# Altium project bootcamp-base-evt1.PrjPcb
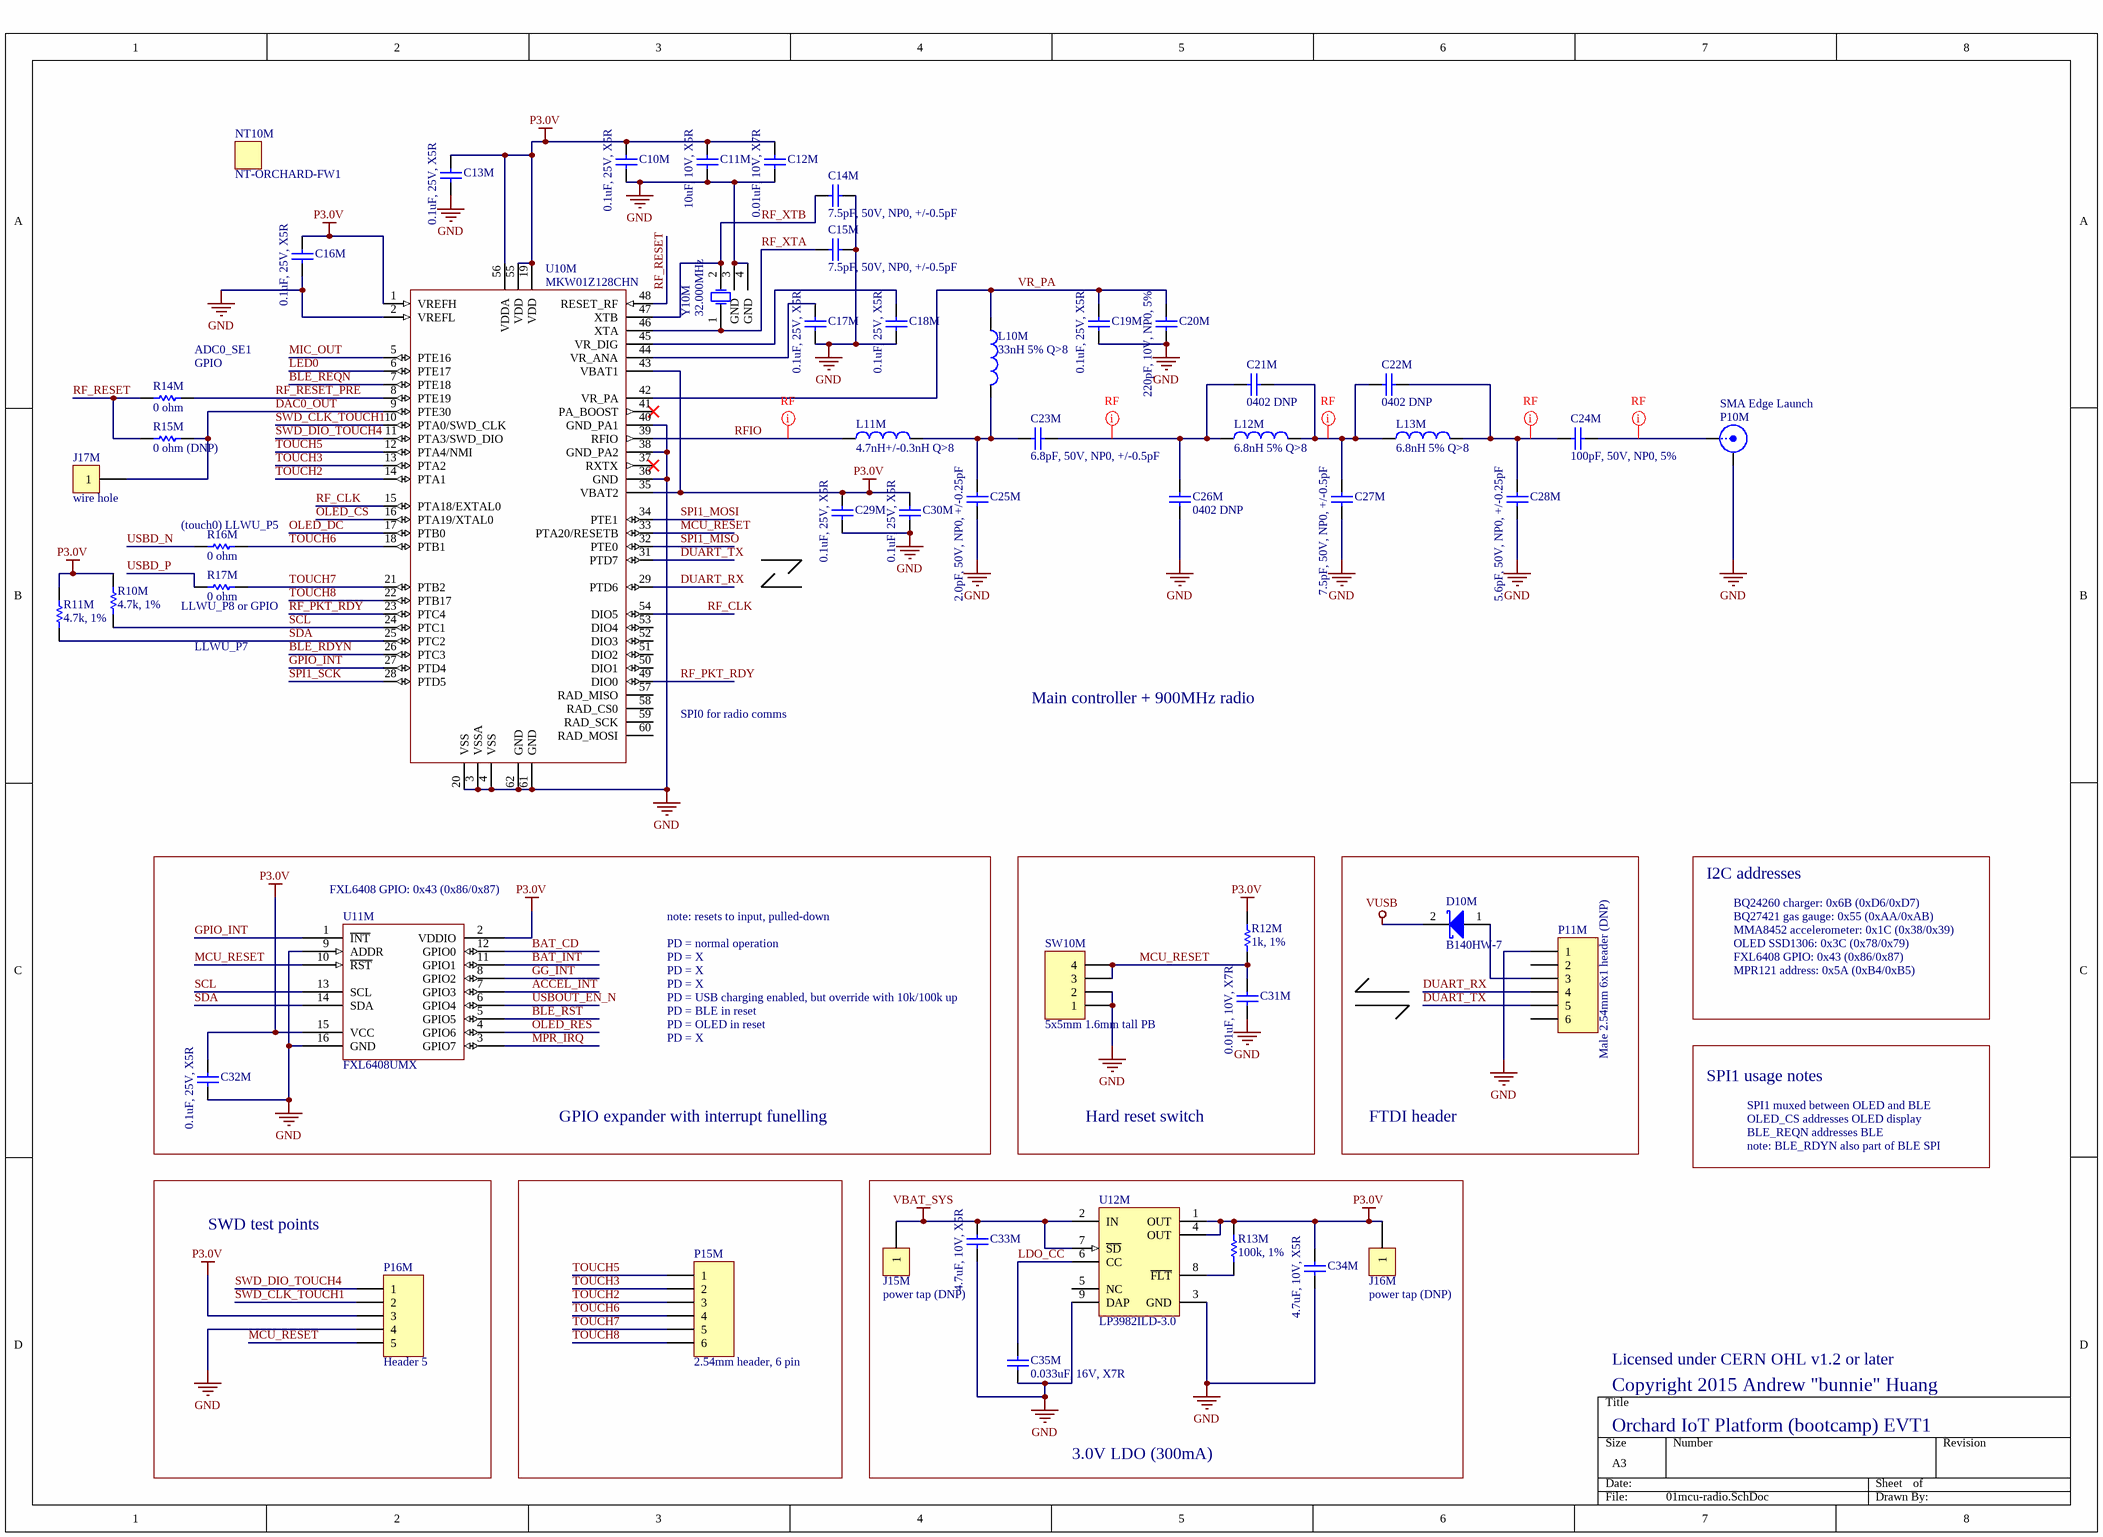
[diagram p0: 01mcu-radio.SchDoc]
7 sheets, 180 parts. Net scope: global (net labels, ports and power ports of the same name join across sheets).
Board files: bootcamp-base-evt1b.PcbDoc, bootcamp-base-evt1-local-routes-handoff.PcbDoc
Sheets:
  01mcu-radio.SchDoc
  02battery.SchDoc
  03sensors.SchDoc
  04oled.SchDoc
  05ble.SchDoc
  06led.SchDoc
  07captouch.SchDoc

## Sheet 01mcu-radio.SchDoc
size A3

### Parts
C10M  0.1uF, 25V, X5R  [CAPC1005N]
C11M  10uF, 10V, X5R  [CAPC1608N]
C12M  0.01uF, 10V, X7R  [CAPC1005N]
C13M  0.1uF, 25V, X5R  [CAPC1005N]
C14M  7.5pF, 50V, NP0, +/-0.5pF  [CAPC1005N]
C15M  7.5pF, 50V, NP0, +/-0.5pF  [CAPC1005N]
C16M  0.1uF, 25V, X5R  [CAPC1005N]
C17M  0.1uF, 25V, X5R  [CAPC1005N]
C18M  0.1uF, 25V, X5R  [CAPC1005N]
C19M  0.1uF, 25V, X5R  [CAPC1005N]
C20M  220pF, 10V, NP0, 5%  [CAPC1005N]
C21M  0402 DNP  [CAPC1005N]
C22M  0402 DNP  [CAPC1005N]
C23M  6.8pF, 50V, NP0, +/-0.5pF  [CAPC1005N]
C24M  100pF, 50V, NP0, 5%  [CAPC1005N]
C25M  2.0pF, 50V, NP0, +/-0.25pF  [CAPC1005N]
C26M  0402 DNP  [CAPC1005N]
C27M  7.5pF, 50V, NP0, +/-0.5pF  [CAPC1005N]
C28M  5.6pF, 50V, NP0, +/-0.25pF  [CAPC1005N]
C29M  0.1uF, 25V, X5R  [CAPC1005N]
C30M  0.1uF, 25V, X5R  [CAPC1005N]
C31M  0.01uF, 10V, X7R  [CAPC1005N]
C32M  0.1uF, 25V, X5R  [CAPC1005N]
C33M  4.7uF, 10V, X5R  [CAPC1608N]
C34M  4.7uF, 10V, X5R  [CAPC1608N]
C35M  0.033uF, 16V, X7R  [CAPC1005N]
D10M  B140HW-7  [SOD123]
J15M  power tap (DNP)  [RESTAP-0603]
J16M  power tap (DNP)  [RESTAP-0603]
J17M  wire hole  [TP_HOLE]
L10M  33nH 5% Q>8  [INDC1608AN]
L11M  4.7nH+/-0.3nH Q>8  [INDC1608AN]
L12M  6.8nH 5% Q>8  [INDC1608AN]
L13M  6.8nH 5% Q>8  [INDC1608AN]
NT10M  NT-ORCHARD-FW1
P10M  SMA Edge Launch  [SMA_EDGELAUNCH]
P11M  Male 2.54mm 6x1 header (DNP)  [HDR1X6]
P15M  2.54mm header, 6 pin  [HDR1X6]
P16M  Header 5  [HDR1X5]
R10M  4.7k, 1%  [RESC1005N]
R11M  4.7k, 1%  [RESC1005N]
R12M  1k, 1%  [RESC1005N]
R13M  100k, 1%  [RESC1005N]
R14M  0 ohm  [RESC1005N]
R15M  0 ohm (DNP)  [RESC1005N]
R16M  0 ohm  [RESC1005N]
R17M  0 ohm  [RESC1005N]
SW10M  5x5mm 1.6mm tall PB  [SWITCH_TS-1187A]
U10M  MKW01Z128CHN  [KINETIS_W_QFN50P800X800X98_HS-57N]
U11M  FXL6408UMX  [FAIRCHILD_UMLP16]
U12M  LP3982ILD-3.0  [LDA08C]
Y10M  32.000MHz  [NDK_NX3225SA]

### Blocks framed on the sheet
GPIO expander with interrupt funelling: C32M U11M
Hard reset switch: C31M R12M SW10M
FTDI header: D10M P11M
SWD test points: P16M
3.0V LDO (300mA): C33M C34M C35M J15M J16M R13M U12M

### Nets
GND: C10M.2 C11M.2 C12M.2 C13M.2 C14M.2 C15M.2 C16M.2 C17M.2 C18M.2 C19M.2 C20M.2 C25M.2 C26M.1 C27M.2 C28M.2 C29M.2 C30M.2 C31M.2 C32M.2 C33M.2 C34M.2 C35M.1 P10M.2(Y) P11M.1 P16M.4 SW10M.1 SW10M.2 U10M.2(VREFL) U10M.3(VSSA) U10M.4(VSS) U10M.20(VSS) U10M.36(GND) U10M.38(GND_PA2) U10M.40(GND_PA1) U10M.61(GND) U10M.62(GND) U11M.9(ADDR) U11M.16(GND) U12M.3(GND) U12M.9(DAP) Y10M.3(GND) Y10M.4(GND)
P3.0V: C10M.1 C11M.1 C12M.1 C13M.1 C16M.1 C29M.1 C30M.1 C32M.1 C34M.1 J16M.1 P16M.3 R10M.2 R11M.2 R12M.1 R13M.1 U10M.1(VREFH) U10M.19(VDD) U10M.35(VBAT2) U10M.43(VBAT1) U10M.55(VDD) U10M.56(VDDA) U11M.2(VDDIO) U11M.15(VCC) U12M.1(OUT) U12M.4(OUT)
VBAT_SYS: C33M.1 J15M.1 U12M.2(IN) U12M.7(~{SD})
VUSB: D10M.2(K)
ACCEL_INT: U11M.7(GPIO3)
BAT_CD: U11M.12(GPIO0)
BAT_INT: U11M.11(GPIO1)
BLE_RDYN: U10M.26(PTC3)
BLE_REQN: U10M.7(PTE18)
BLE_RST: U11M.5(GPIO5)
DAC0_OUT: J17M.1 R15M.2 U10M.9(PTE30)
DUART_RX: P11M.4 U10M.29(PTD6)
DUART_TX: P11M.5 U10M.31(PTD7)
GG_INT: U11M.8(GPIO2)
GPIO_INT: U10M.27(PTD4) U11M.1(~{INT})
LDO_CC: C35M.2 U12M.6(CC)
LED0: U10M.6(PTE17)
MCU_RESET: C31M.1 P16M.5 R12M.2 SW10M.3 SW10M.4 U10M.33(PTA20/RESETB) U11M.10(~{RST})
MIC_OUT: U10M.5(PTE16)
MPR_IRQ: U11M.3(GPIO7)
OLED_CS: U10M.16(PTA19/XTAL0)
OLED_DC: U10M.17(PTB0)
OLED_RES: U11M.4(GPIO6)
RF_CLK: U10M.15(PTA18/EXTAL0) U10M.54(DIO5)
RF_PKT_RDY: U10M.23(PTC4) U10M.49(DIO0)
RF_RESET: R14M.1 R15M.1 U10M.48(RESET_RF)
RF_RESET_PRE: R14M.2 U10M.8(PTE19)
RF_XTA: C15M.1 U10M.46(XTA) Y10M.1(OSC1)
RF_XTB: C14M.1 U10M.47(XTB) Y10M.2(OSC2)
RFIO: L11M.1 U10M.39(RFIO)
SCL: R10M.1 U10M.24(PTC1) U11M.13(SCL)
SDA: R11M.1 U10M.25(PTC2) U11M.14(SDA)
SPI1_MISO: U10M.32(PTE0)
SPI1_MOSI: U10M.34(PTE1)
SPI1_SCK: U10M.28(PTD5)
SWD_CLK_TOUCH1: P16M.2 U10M.10(PTA0/SWD_CLK)
SWD_DIO_TOUCH4: P16M.1 U10M.11(PTA3/SWD_DIO)
TOUCH2: P15M.3 U10M.14(PTA1)
TOUCH3: P15M.2 U10M.13(PTA2)
TOUCH5: P15M.1 U10M.12(PTA4/NMI)
TOUCH6: P15M.4 R16M.2 U10M.18(PTB1)
TOUCH7: P15M.5 R17M.2 U10M.21(PTB2)
TOUCH8: P15M.6 U10M.22(PTB17)
USBD_N: R16M.1
USBD_P: R17M.1
USBOUT_EN_N: U11M.6(GPIO4)
VR_PA: C19M.1 C20M.1 L10M.1 U10M.42(VR_PA)
NetC17M_1: C17M.1 U10M.44(VR_ANA)
NetC18M_1: C18M.1 U10M.45(VR_DIG)
NetC21M_1: C21M.1 C23M.2 C26M.2 L12M.1
NetC21M_2: C21M.2 C22M.1 C27M.1 L12M.2 L13M.1
NetC22M_2: C22M.2 C24M.1 C28M.1 L13M.2
NetC23M_1: C23M.1 C25M.1 L10M.2 L11M.2
NetC24M_2: C24M.2 P10M.1(X)
NetD10M_1: D10M.1(A) P11M.3
NetR13M_2: R13M.2 U12M.8(~{FLT})

Not connected (* = marked no-connect by the designer): P11M 2 6; U10M 37(RXTX)* 41(PA_BOOST)* 50(DIO1) 51(DIO2) 52(DIO3) 53(DIO4) 57(RAD_MISO) 58(RAD_CS0) 59(RAD_SCK) 60(RAD_MOSI); U12M 5(NC)

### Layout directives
net class RF: NetC21M_1, NetC21M_2, NetC22M_2, NetC24M_2, RFIO

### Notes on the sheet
- (near R14M) ADC0_SE1
- (near R14M) GPIO
- (near R16M) (touch0) LLWU_P5
- (near R17M) LLWU_P8 or GPIO
- LLWU_P7
- SPI0 for radio comms
- Main controller + 900MHz radio
- I2C addresses
- (near U11M) FXL6408 GPIO: 0x43 (0x86/0x87)
- note: resets to input, pulled-down
- PD = normal operation
- BQ24260 charger: 0x6B (0xD6/0xD7)
- BQ27421 gas gauge: 0x55 (0xAA/0xAB)
- MMA8452 accelerometer: 0x1C (0x38/0x39)
- OLED SSD1306: 0x3C (0x78/0x79)
- PD = X
- PD = USB charging enabled, but override with 10k/100k up
- PD = BLE in reset
- FXL6408 GPIO: 0x43 (0x86/0x87)
- MPR121 address: 0x5A (0xB4/0xB5)
- PD = OLED in reset
- SPI1 usage notes
- SPI1 muxed between OLED and BLE
- OLED_CS addresses OLED display
- BLE_REQN addresses BLE
- note: BLE_RDYN also part of BLE SPI
- Licensed under CERN OHL v1.2 or later
- Copyright 2015 Andrew "bunnie" Huang
- Orchard IoT Platform (bootcamp) EVT1

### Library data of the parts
C10M C13M C16M C17M C18M C19M C29M C30M C32M = Cap Semi: Capacitor (Semiconductor SIM Model); MPN: CL05A104KA5NNNC; VENDOR: Samsung; MYPN: C-104-25-X5R-0402
C11M = Cap Semi: Capacitor (Semiconductor SIM Model); MPN: CL10A106KP8NNND; VENDOR: Samsung; MYPN: C-106-10-X5R-0603
C12M C31M = Cap Semi: Capacitor (Semiconductor SIM Model); MPN: CL05B103KP5NNNC; VENDOR: Samsung; MYPN: C-103-10-X7R-0402
C14M C15M C27M = Cap Semi: Capacitor (Semiconductor SIM Model); MPN: 0402CG7R5D500NT; VENDOR: Fenghua; MYPN: C-7R5-50-NP0-0402
C20M = Cap Semi: Capacitor (Semiconductor SIM Model); MPN: 0402CG221J100NT; VENDOR: Fenghua; MYPN: C-221-10-NP0-0402
C21M C22M C26M = Cap Semi: Capacitor (Semiconductor SIM Model); MPN: None; MYPN: C-DNP-0402
C23M = Cap Semi: Capacitor (Semiconductor SIM Model); MPN: 0402CG6R8D500NT; VENDOR: Fenghua; MYPN: C-6R8-50-NP0-0402
C24M = Cap Semi: Capacitor (Semiconductor SIM Model); MPN: 0402CG101J500NT; VENDOR: Fenghua; MYPN: C-101-50-NP0-0402
C25M = Cap Semi: Capacitor (Semiconductor SIM Model); MPN: 0402CG2R0C500NT; VENDOR: Fenghua; MYPN: C-2R0-50-NP0-0402
C28M = Cap Semi: Capacitor (Semiconductor SIM Model); MPN: 0402CG5R6C500NT; VENDOR: Fenghua; MYPN: C-5R6-50-NP0-0402
C33M C34M = Cap Semi: Capacitor (Semiconductor SIM Model); MPN: CL10A475KP8NNNC; VENDOR: Samsung; MYPN: C-475-10-X5R-0603
C35M = Cap Semi: Capacitor (Semiconductor SIM Model); MPN: CL05B333KO5NNND; VENDOR: Samsung; MYPN: C-333-16-X7R-0402
D10M = D Schottky: Schottky Diode; VENDOR: Diodes Incorporated; MYPN: D-S-01-40-0p5-SOD123
J15M J16M = CON1: Connector; MYPN: J-TP-PWRTAP-0603
J17M = CON1: Connector; MPN: DNP; MYPN: J-TP-HOLE1
L10M = Inductor: chip inductor, 0603; MPN: VHF160808H33NJT; VENDOR: Fenghua; MYPN: L-33N-MLC-0603
L11M = Inductor: chip inductor, 0603; MPN: VHF160808H4N7ST; VENDOR: Fenghua; MYPN: L-4N7-MLC-0603
L12M L13M = Inductor: chip inductor, 0603; MPN: VHF160808H6N8JT; VENDOR: Fenghua; MYPN: L-6N8-MLC-0603
NT10M = NOTE: Placeholder for non-electrical BOM items; MPN: Orchard Firmware EVT1; VENDOR: Sutajio Ko-Usagi PTE LTD
P10M = BNC: 50 ohm SMA Edge Launch Connector; MPN: CONSMA003.062 (please find alt); MYPN: J-RF-SMA-EDGE-50OHM; VENDOR: Any/open
P11M = Header 6: Header, 6-Pin; MYPN: J-HDR-2.54-6x1-STD-DNP
P15M = Header 6: Header, 6-Pin; MYPN: DNP
P16M = Header 5: Header, 5-Pin; MPN: DNP; MYPN: J-HDR-2.54-5x1-STD-DNP
R10M R11M = Res1: Resistor; MPN: RS02U472FT; VENDOR: Fenghua; MYPN: R-472-1P-1_16W-0402
R12M = Res1: Resistor; MPN: RS02U102FT; VENDOR: Fenghua; MYPN: R-102-1P-1_16W-0402
R13M = Res1: Resistor; MPN: RS02U104FT; VENDOR: Fenghua; MYPN: R-104-1P-1_16W-0402
R14M R16M R17M = Res1: Resistor; MPN: ANY-0402-0OHM; VENDOR: ANY; MYPN: R-000-1_4W-0402
R15M = Res1: Resistor; MYPN: R-000-1_4W-0402-DNP
SW10M = Header 4: Chi Fung TS-1187A; MPN: SW-PB-5X5-1.6; VENDOR: Kangdeli
U10M = MKW01Z128CHN: Freescale Kinetis Integrated Radio + MCU, < 1GHz; MYPN: UMKW01Z128XX
U11M = FXL6408: 8-bit I2C GPIO expander; MYPN: UFXL6408UMX; VENDOR: Fairchild Semiconductor
U12M = LP3982ILD-3.0: Micropower, Ultra Low-Dropout, Low-Noise, 300mA CMOS Regulator; Manufacturer: National Semiconductor; MPN: LP3982ILD-3.0/NOPB; CompType: LDO IC; PackageTopMarking: XYTT*LTB; PowerWise: N; MYPN: ULP3982ILD-3.0/NOPB; VENDOR: National Semicondutor
Y10M = XTAL: 32 MHz, 7pF CL 10ppm 3225 SMD crystal; MPN: SJSMD3232M012F10; VENDOR: Songji; MYPN: X-32.000M-SONGJI

## Sheet 02battery.SchDoc
size A3
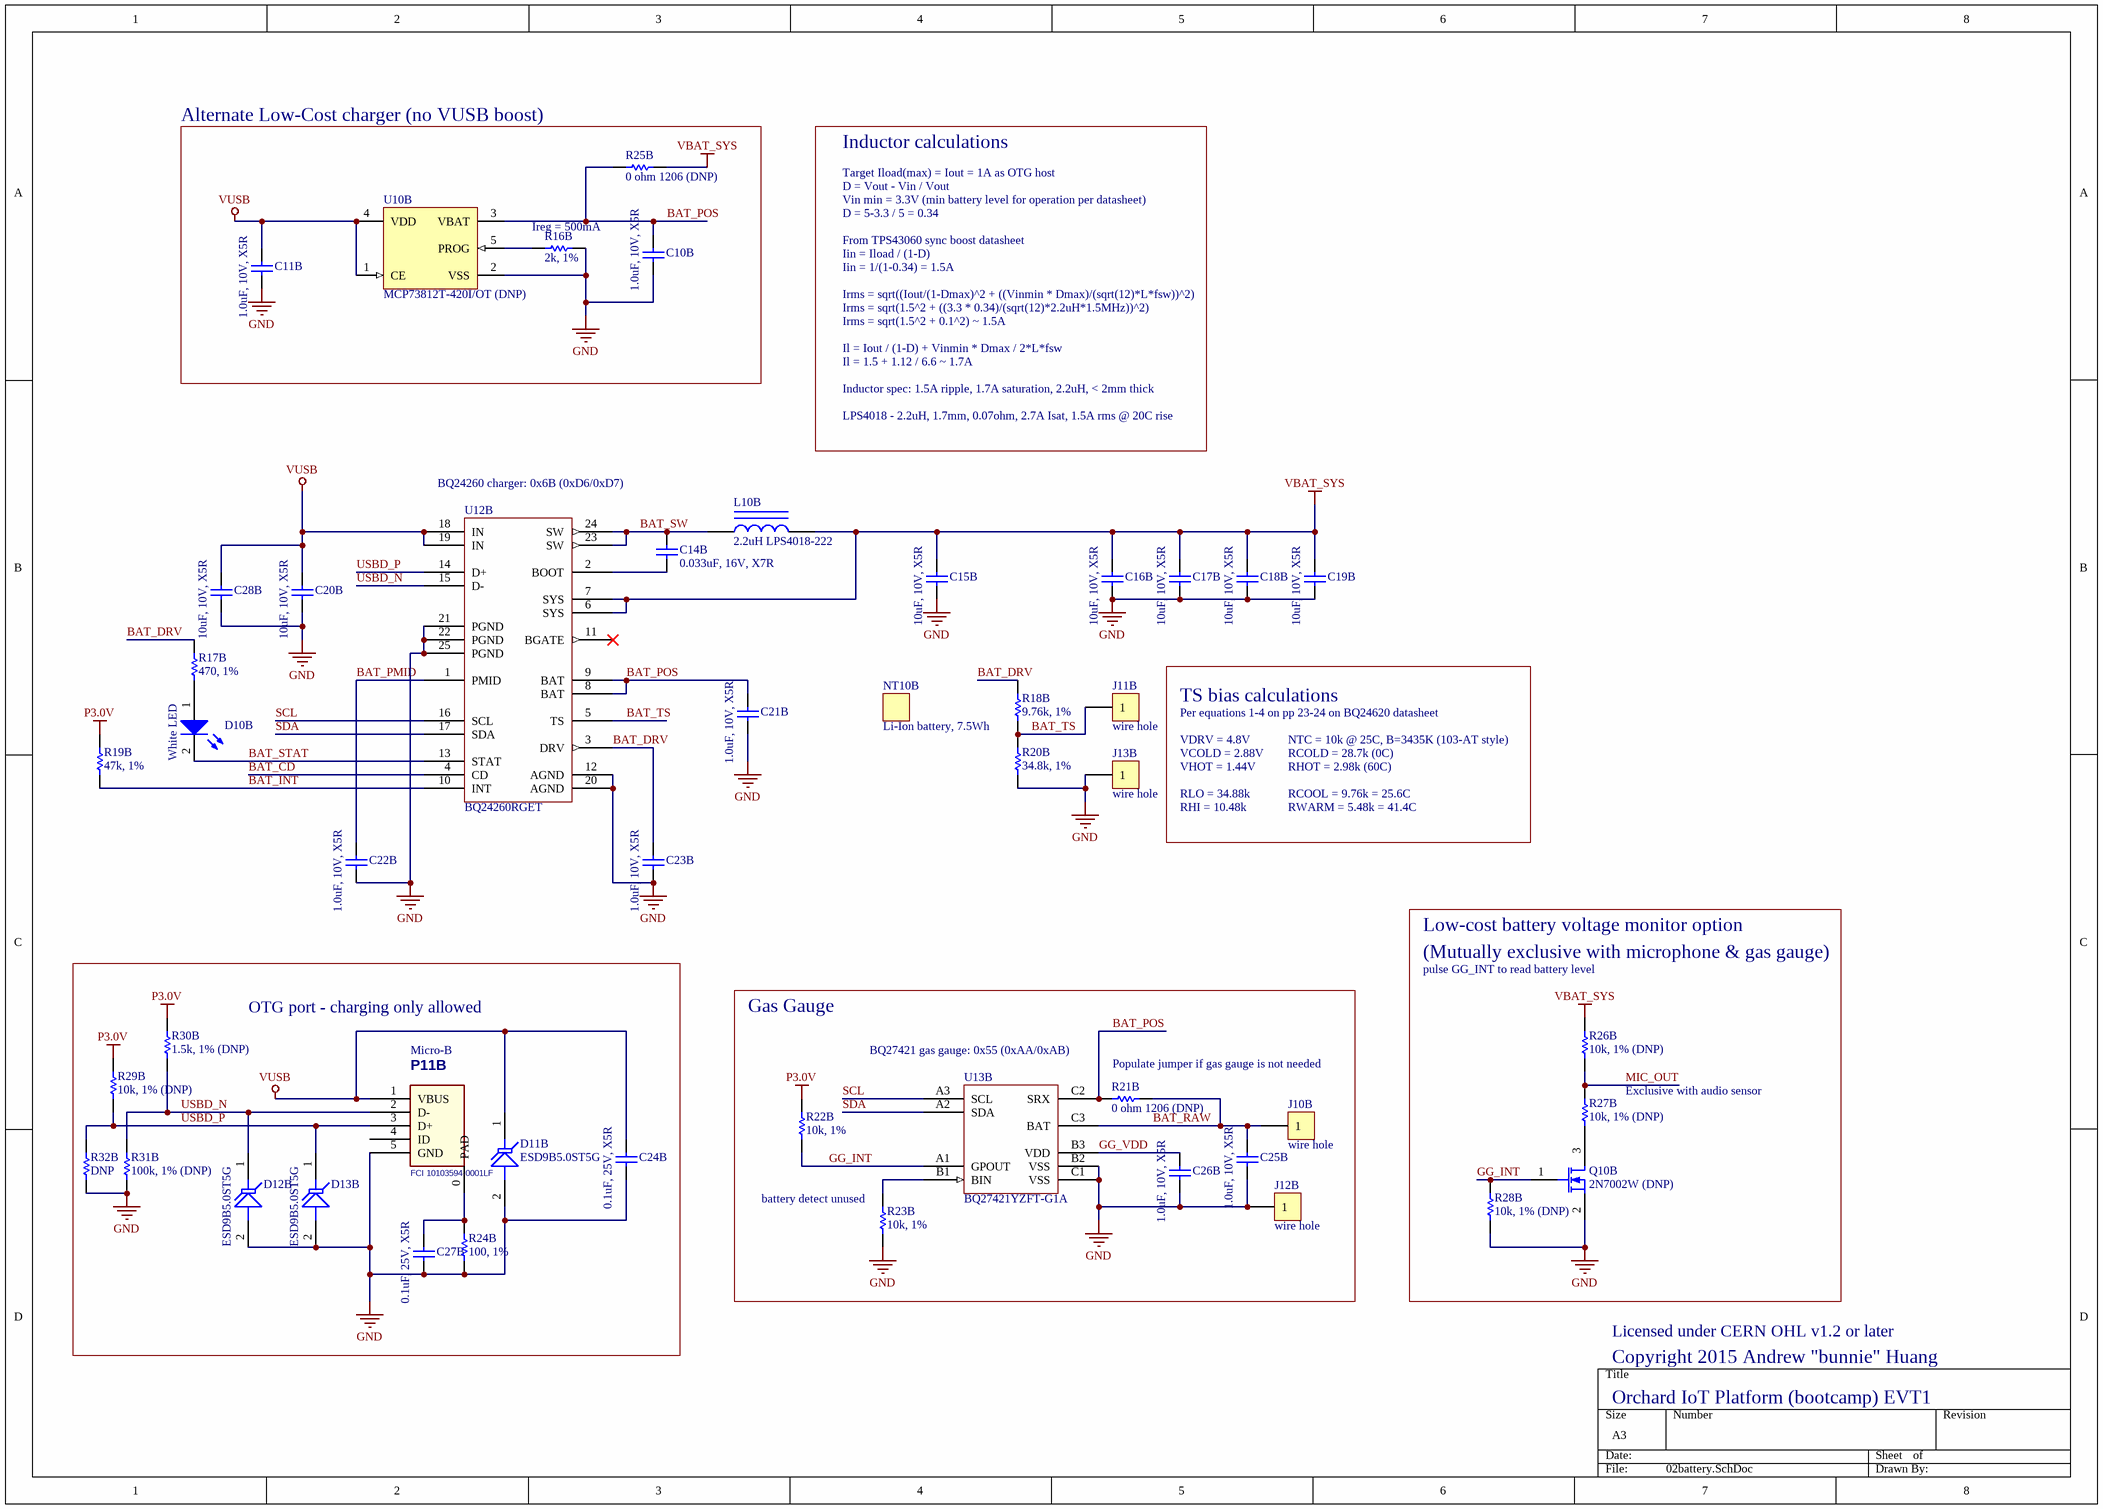
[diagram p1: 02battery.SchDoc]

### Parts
C10B  1.0uF, 10V, X5R  [CAPC1005N]
C11B  1.0uF, 10V, X5R  [CAPC1005N]
C14B  0.033uF, 16V, X7R  [CAPC1005N]
C15B  10uF, 10V, X5R  [CAPC1608N]
C16B  10uF, 10V, X5R  [CAPC1608N]
C17B  10uF, 10V, X5R  [CAPC1608N]
C18B  10uF, 10V, X5R  [CAPC1608N]
C19B  10uF, 10V, X5R  [CAPC1608N]
C20B  10uF, 10V, X5R  [CAPC1608N]
C21B  1.0uF, 10V, X5R  [CAPC1005N]
C22B  1.0uF, 10V, X5R  [CAPC1005N]
C23B  1.0uF, 10V, X5R  [CAPC1005N]
C24B  0.1uF, 25V, X5R  [CAPC1005N]
C25B  1.0uF, 10V, X5R  [CAPC1005N]
C26B  1.0uF, 10V, X5R  [CAPC1005N]
C27B  0.1uF, 25V, X5R  [CAPC1005N]
C28B  10uF, 10V, X5R  [CAPC1608N]
D10B  White LED  [CD2012-0805]
D11B  ESD9B5.0ST5G  [SOD-923]
D12B  ESD9B5.0ST5G  [SOD-923]
D13B  ESD9B5.0ST5G  [SOD-923]
J10B  wire hole  [TP_HOLE]
J11B  wire hole  [TP_HOLE]
J12B  wire hole  [TP_HOLE]
J13B  wire hole  [TP_HOLE]
L10B  2.2uH LPS4018-222  [COILCRAFT_LPS4018]
NT10B  Li-Ion battery, 7.5Wh
P11B  FCI 10103594-0001LF  [USB_MICRO_B_SMT]
Q10B  2N7002W (DNP)  [SOT323-3AN]
R16B  2k, 1%  [RESC1005N]
R17B  470, 1%  [RESC1005N]
R18B  9.76k, 1%  [RESC1005N]
R19B  47k, 1%  [RESC1005N]
R20B  34.8k, 1%  [RESC1005N]
R21B  0 ohm 1206 (DNP)  [RESC3216N]
R22B  10k, 1%  [RESC1005N]
R23B  10k, 1%  [RESC1005N]
R24B  100, 1%  [RESC1005N]
R25B  0 ohm 1206 (DNP)  [RESC3216N]
R26B  10k, 1% (DNP)  [RESC1005N]
R27B  10k, 1% (DNP)  [RESC1005N]
R28B  10k, 1% (DNP)  [RESC1005N]
R29B  10k, 1% (DNP)  [RESC1005N]
R30B  1.5k, 1% (DNP)  [RESC1005N]
R31B  100k, 1% (DNP)  [RESC1005N]
R32B  DNP  [RESC1005N]
U10B  MCP73812T-420I/OT (DNP)  [SOT-23-OT5_N]
U12B  BQ24260RGET  [QFN50P400X400-24VBN]
U13B  BQ27421YZFT-G1A  [TI_YZF_S_XBGA_N9]

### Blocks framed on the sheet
Alternate Low-Cost charger (no VUSB boost): C10B C11B R16B R25B U10B
OTG port - charging only allowed: C24B C27B D11B D12B D13B P11B R24B R29B R30B R31B R32B
Gas Gauge: C25B C26B J10B J12B R21B R22B R23B U13B

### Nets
GND: C10B.2 C11B.2 C15B.2 C16B.2 C17B.2 C18B.2 C19B.2 C20B.2 C21B.2 C22B.2 C23B.2 C24B.2 C25B.2 C26B.2 C27B.2 C28B.2 D11B.2(A) D12B.2(A) D13B.2(A) J12B.1 J13B.1 P11B.5(GND) Q10B.2(S) R16B.2 R20B.1 R23B.1 R24B.2 R28B.1 R31B.2 R32B.2 U10B.2(VSS) U12B.12(AGND) U12B.20(AGND) U12B.21(PGND) U12B.22(PGND) U12B.25(PGND) U13B.B2(VSS) U13B.C1(VSS)
P3.0V: R19B.2 R22B.2 R29B.2 R30B.2
VBAT_SYS: C15B.1 C16B.1 C17B.1 C18B.1 C19B.1 L10B.2 R25B.2 R26B.2 U12B.6(SYS) U12B.7(SYS)
VUSB: C11B.1 C20B.1 C24B.1 C28B.1 D11B.1(K) P11B.1(VBUS) U10B.1(CE) U10B.4(VDD) U12B.18(IN) U12B.19(IN)
BAT_CD: U12B.4(CD)
BAT_DRV: C23B.1 R17B.1 R18B.2 U12B.3(DRV)
BAT_INT: R19B.1 U12B.10(INT)
BAT_PMID: C22B.1 U12B.1(PMID)
BAT_POS: C10B.1 C21B.1 R21B.1 R25B.1 U10B.3(VBAT) U12B.8(BAT) U12B.9(BAT) U13B.C2(SRX)
BAT_RAW: C25B.1 J10B.1 R21B.2 U13B.C3(BAT)
BAT_STAT: D10B.2(K) U12B.13(STAT)
BAT_SW: C14B.2 L10B.1 U12B.23(SW) U12B.24(SW)
BAT_TS: J11B.1 R18B.1 R20B.2 U12B.5(TS)
GG_INT: Q10B.1(G) R22B.1 R28B.2 U13B.A1(GPOUT)
GG_VDD: C26B.1 U13B.B3(VDD)
MIC_OUT: R26B.1 R27B.2
SCL: U12B.16(SCL) U13B.A3(SCL)
SDA: U12B.17(SDA) U13B.A2(SDA)
USBD_N: D12B.1(K) P11B.2(D-) R30B.1 R31B.1 U12B.15(D-)
USBD_P: D13B.1(K) P11B.3(D+) R29B.1 R32B.1 U12B.14(D+)
NetC14B_1: C14B.1 U12B.2(BOOT)
NetC27B_1: C27B.1 P11B.0(PAD) R24B.1
NetD10B_1: D10B.1(A) R17B.2
NetQ10B_3: Q10B.3(D) R27B.1
NetR16B_1: R16B.1 U10B.5(PROG)
NetR23B_2: R23B.2 U13B.B1(BIN)

Not connected (* = marked no-connect by the designer): P11B 4(ID); U12B 11(BGATE)*

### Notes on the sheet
- Target Iload(max) = Iout = 1A as OTG host
- Inductor calculations
- (near R16B) Ireg = 500mA
- D = Vout - Vin / Vout
- D = 5-3.3 / 5 = 0.34
- Vin min = 3.3V (min battery level for operation per datasheet)
- From TPS43060 sync boost datasheet
- Iin = Iload / (1-D)
- Irms = sqrt((Iout/(1-Dmax)^2 + ((Vinmin * Dmax)/(sqrt(12)*L*fsw))^2)
- Iin = 1/(1-0.34) = 1.5A
- Irms = sqrt(1.5^2 + ((3.3 * 0.34)/(sqrt(12)*2.2uH*1.5MHz))^2)
- Il = Iout / (1-D) + Vinmin * Dmax / 2*L*fsw
- Irms = sqrt(1.5^2 + 0.1^2) ~ 1.5A
- Il = 1.5 + 1.12 / 6.6 ~ 1.7A
- Inductor spec: 1.5A ripple, 1.7A saturation, 2.2uH, < 2mm thick
- LPS4018 - 2.2uH, 1.7mm, 0.07ohm, 2.7A Isat, 1.5A rms @ 20C rise
- BQ24260 charger: 0x6B (0xD6/0xD7)
- Per equations 1-4 on pp 23-24 on BQ24620 datasheet
- TS bias calculations
- VDRV = 4.8V
- VCOLD = 2.88V
- VHOT = 1.44V
- NTC = 10k @ 25C, B=3435K (103-AT style)
- RCOLD = 28.7k (0C)
- RHOT = 2.98k (60C)
- RHI = 10.48k
- RLO = 34.88k
- RCOOL = 9.76k = 25.6C
- RWARM = 5.48k = 41.4C
- Low-cost battery voltage monitor option
- (Mutually exclusive with microphone & gas gauge)
- pulse GG_INT to read battery level
- (near P11B) Micro-B
- BQ27421 gas gauge: 0x55 (0xAA/0xAB)
- (near R21B) Populate jumper if gas gauge is not needed
- Exclusive with audio sensor
- (near R23B) battery detect unused
- Licensed under CERN OHL v1.2 or later
- Copyright 2015 Andrew "bunnie" Huang
- Orchard IoT Platform (bootcamp) EVT1

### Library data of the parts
C10B C11B C21B C22B C23B C25B C26B = Cap Semi: Capacitor (Semiconductor SIM Model); MPN: CL05A105KP5NNND; VENDOR: Samsung; MYPN: C-105-10-X5R-0402
C14B = Cap Semi: as C35M on sheet 01mcu-radio
C15B C16B C17B C18B C19B C20B C28B = Cap Semi: as C11M on sheet 01mcu-radio
C24B C27B = Cap Semi: as C10M on sheet 01mcu-radio
D10B = LED2: White LED 0805; MPN: WLUW0805A-612-I15; MYPN: D-LED-WHITE1-0805; VENDOR: Wenling
D11B D12B D13B = Tranzorb: TVS Diode, 5V; VENDOR: On Semiconductor; MYPN: D-ESD-5.0-SOD-923
J10B J11B J12B J13B = CON1: Connector; MPN: DNP; MYPN: J-TP-HOLE1
L10B = Inductor Iron: Magnetic-Core Inductor; MPN: LPS4018-222NRC; VENDOR: Coilcraft; MYPN: L-LPS4018-222
NT10B = NOTE: 2100mAh Tx61x58mm battery C=2.1A (nominal) NTC = 10k, B=3435; MPN: TBD but e.g. GM055085-PCB; MYPN: NT-LION-2100-5-50-85-HC; VENDOR: TBD
P11B = USB_MINI-AB_1: Micro USB B type connector; VENDOR: FCI/BERG; MYPN: J-MICROUSB-SMT-FCI
Q10B = MOSFET-N: N-Channel MOSFET; MYPN: Q-NMOS-LP-LV-DNP
R16B = Res1: Resistor; MPN: RS02U202FT; VENDOR: Fenghua; MYPN: R-202-1P-1_16W-0402
R17B = Res1: Resistor; MPN: RS02U471FT; VENDOR: Fenghua; MYPN: R-471-1P-1_16W-0402
R18B = Res1: Resistor; MPN: RS02U9761FT; VENDOR: Fenghua; MYPN: R-9761-1P-1_16W-0402
R19B = Res1: Resistor; MPN: RS02U473FT; VENDOR: Fenghua; MYPN: R-473-1P-1_16W-0402
R20B = Res1: Resistor; MPN: RS02U3482FT; VENDOR: Fenghua; MYPN: R-3482-1P-1_16W-0402
R21B R25B = Res1: Resistor; MYPN: R-000-1_4W-1206-DNP
R22B R23B = Res1: Resistor; MPN: RS02U103FT; VENDOR: Fenghua; MYPN: R-103-1P-1_16W-0402
R24B = Res1: Resistor; MPN: RS02U101FT; VENDOR: Fenghua; MYPN: R-101-1P-1_16W-0402
R26B R27B R28B R29B = Res1: Resistor; MYPN: R-103-1P-1_16W-0402-DNP
R30B = Res1: Resistor; MYPN: R-152-1P-1_16W-0402-DNP
R31B = Res1: Resistor; MYPN: R-104-1P-1_16W-0402-DNP
R32B = Res1: Resistor
U10B = MCP73812T-420I/OT: Simple, Miniature Single-Cell, Fully Integrated Li-Ion/Li-Polymer Charge Management Controller, 4.2V, 5-Pin SOT-23, Industrial Temperature, Tape and Reel; Manufacturer: Microchip; VENDOR: Microchip Technology, Inc.; MYPN: UMCP73812T-420I/OT-DNP
U12B = BQ24260/1/2RGE: 3A, 30V host-controlled single cell Li-ion battery charger; VENDOR: Texas Instruments
U13B = BQ27421YZFT-G1A: System-side Impedance Track Gas Gauge; VENDOR: Texas Instruments; MYPN: UBQ27421YZFT-G1A

## Sheet 03sensors.SchDoc
size A
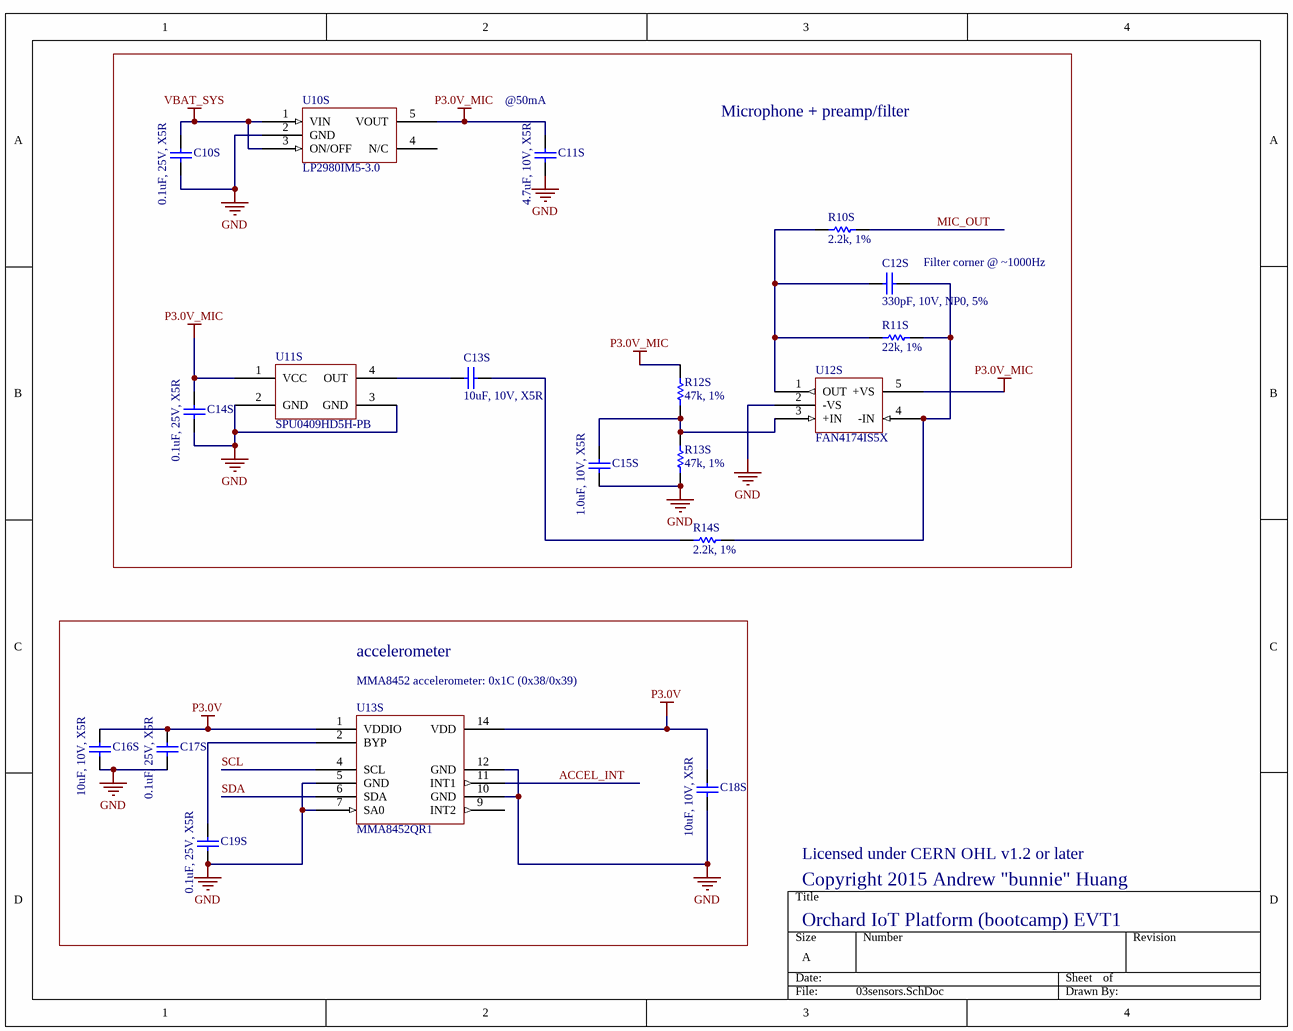
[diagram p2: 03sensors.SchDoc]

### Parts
C10S  0.1uF, 25V, X5R  [CAPC1005N]
C11S  4.7uF, 10V, X5R  [CAPC1608N]
C12S  330pF, 10V, NP0, 5%  [CAPC1005N]
C13S  10uF, 10V, X5R  [CAPC1608N]
C14S  0.1uF, 25V, X5R  [CAPC1005N]
C15S  1.0uF, 10V, X5R  [CAPC1005N]
C16S  10uF, 10V, X5R  [CAPC1608N]
C17S  0.1uF, 25V, X5R  [CAPC1005N]
C18S  10uF, 10V, X5R  [CAPC1608N]
C19S  0.1uF, 25V, X5R  [CAPC1005N]
R10S  2.2k, 1%  [RESC1005N]
R11S  22k, 1%  [RESC1005N]
R12S  47k, 1%  [RESC1005N]
R13S  47k, 1%  [RESC1005N]
R14S  2.2k, 1%  [RESC1005N]
U10S  LP2980IM5-3.0  [SOT23-5AN]
U11S  SPU0409HD5H-PB  [KNOWLES_SPU0409HD5H-PB]
U12S  FAN4174IS5X  [SOT23-5AN]
U13S  MMA8452QR1  [FSC_QFN_3x3x1_16_2077-02]

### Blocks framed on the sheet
Microphone + preamp/filter: C10S C11S C12S C13S C14S C15S R10S R11S R12S R13S R14S U10S U11S U12S
accelerometer: C16S C17S C18S C19S U13S

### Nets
GND: C10S.2 C11S.2 C14S.2 C15S.2 C16S.2 C17S.2 C18S.2 C19S.2 R13S.1 U10S.2(GND) U11S.2(GND) U11S.3(GND) U12S.2(-VS) U13S.5(GND) U13S.7(SA0) U13S.10(GND) U13S.12(GND)
P3.0V: C16S.1 C17S.1 C18S.1 U13S.1(VDDIO) U13S.14(VDD)
P3.0V_MIC: C11S.1 C14S.1 R12S.2 U10S.5(VOUT) U11S.1(VCC) U12S.5(+VS)
VBAT_SYS: C10S.1 U10S.1(VIN) U10S.3(ON/OFF)
ACCEL_INT: U13S.11(INT1)
MIC_OUT: R10S.1
SCL: U13S.4(SCL)
SDA: U13S.6(SDA)
NetC12S_1: C12S.1 R10S.2 R11S.2 U12S.1(OUT)
NetC12S_2: C12S.2 R11S.1 R14S.1 U12S.4(-IN)
NetC13S_1: C13S.1 U11S.4(OUT)
NetC13S_2: C13S.2 R14S.2
NetC15S_1: C15S.1 R12S.1 R13S.2 U12S.3(+IN)
NetC19S_1: C19S.1 U13S.2(BYP)

Not connected (* = marked no-connect by the designer): U10S 4(N/C); U13S 9(INT2)

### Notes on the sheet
- (near C11S) @50mA
- (near C12S) Filter corner @
  000Hz
- (near U13S) MMA8452 accelerometer: 0x1C (0x38/0x39)
- Licensed under CERN OHL v1.2 or later
- Copyright 2015 Andrew "bunnie" Huang
- Orchard IoT Platform (bootcamp) EVT1

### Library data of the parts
C10S C14S C17S C19S = Cap Semi: as C10M on sheet 01mcu-radio
C11S = Cap Semi: as C33M on sheet 01mcu-radio
C12S = Cap Semi: Capacitor (Semiconductor SIM Model); MPN: 0402CG331J100NT; VENDOR: Fenghua; MYPN: C-331-10-NP0-0402
C13S C16S C18S = Cap Semi: as C11M on sheet 01mcu-radio
C15S = Cap Semi: as C10B on sheet 02battery
R10S R14S = Res1: Resistor; MPN: RS02U222FT; VENDOR: Fenghua; MYPN: R-222-1P-1_16W-0402
R11S = Res1: Resistor; MPN: RS02U223FT; VENDOR: Fenghua; MYPN: R-223-1P-1_16W-0402
R12S R13S = Res1: as R19B on sheet 02battery
U10S = LP2980M5: 50 mA SOT-23 regulator; VENDOR: TI; MYPN: ULP2980IM5-3.0
U11S = SPU0409HD5H-PB: Knowles MEMS silicon microphone; MPN: SPU0409HD5H-PB-7; MYPN: USPU0409HD5H-PB-7; VENDOR: Knowles Electronics
U12S = FAN4174IS5X: Rail-to-rail single CMOS op-amp, 5V, 3.7MHz GBW; VENDOR: Fairchild Semiconductor; MYPN: UFAN4174IS5X
U13S = MMA8452QR1: 3-axis, 12-bit/8-bit digital accelerometer; MPN: MMA8452QT; MYPN: UMMA8452QT; VENDOR: Freescale Semiconductor

## Sheet 04oled.SchDoc
size A
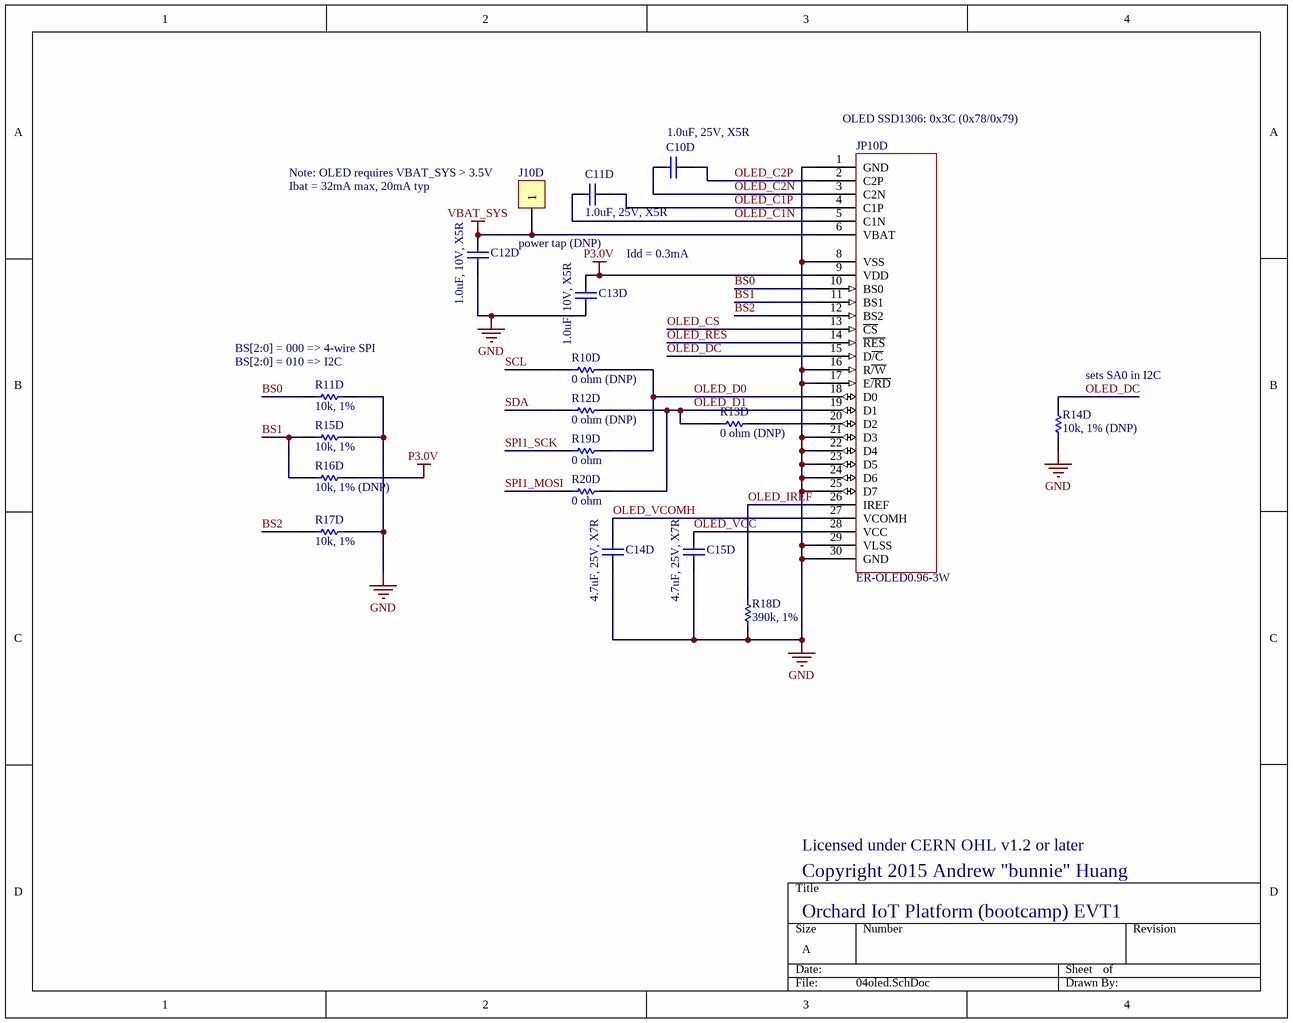
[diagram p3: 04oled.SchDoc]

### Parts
C10D  1.0uF, 25V, X5R  [CAPC1608N]
C11D  1.0uF, 25V, X5R  [CAPC1608N]
C12D  1.0uF, 10V, X5R  [CAPC1005N]
C13D  1.0uF, 10V, X5R  [CAPC1005N]
C14D  4.7uF, 25V, X7R  [CAPC2012N]
C15D  4.7uF, 25V, X7R  [CAPC2012N]
J10D  power tap (DNP)  [RESTAP-0603]
JP10D  ER-OLED0.96-3W  [ER-OLED0.96-FOLD]
R10D  0 ohm (DNP)  [RESC1005N]
R11D  10k, 1%  [RESC1005N]
R12D  0 ohm (DNP)  [RESC1005N]
R13D  0 ohm (DNP)  [RESC1005N]
R14D  10k, 1% (DNP)  [RESC1005N]
R15D  10k, 1%  [RESC1005N]
R16D  10k, 1% (DNP)  [RESC1005N]
R17D  10k, 1%  [RESC1005N]
R18D  390k, 1%  [RESC1005N]
R19D  0 ohm  [RESC1005N]
R20D  0 ohm  [RESC1005N]

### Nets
GND: C12D.2 C13D.2 C14D.2 C15D.2 JP10D.1(GND) JP10D.8(VSS) JP10D.16(R~{/W}) JP10D.17(E~{/RD}) JP10D.21(D3) JP10D.22(D4) JP10D.23(D5) JP10D.24(D6) JP10D.25(D7) JP10D.29(VLSS) JP10D.30(GND) R11D.1 R14D.2 R15D.1 R17D.1 R18D.2
P3.0V: C13D.1 JP10D.9(VDD) R16D.1
VBAT_SYS: C12D.1 J10D.1 JP10D.6(VBAT)
BS0: JP10D.10(BS0) R11D.2
BS1: JP10D.11(BS1) R15D.2 R16D.2
BS2: JP10D.12(BS2) R17D.2
OLED_C1N: C11D.1 JP10D.5(C1N)
OLED_C1P: C11D.2 JP10D.4(C1P)
OLED_C2N: C10D.1 JP10D.3(C2N)
OLED_C2P: C10D.2 JP10D.2(C2P)
OLED_CS: JP10D.13(~{CS})
OLED_D0: JP10D.18(D0) R10D.1 R19D.1
OLED_D1: JP10D.19(D1) R12D.1 R13D.2 R20D.1
OLED_DC: JP10D.15(D~{/C}) R14D.1
OLED_IREF: JP10D.26(IREF) R18D.1
OLED_RES: JP10D.14(~{RES})
OLED_VCC: C15D.1 JP10D.28(VCC)
OLED_VCOMH: C14D.1 JP10D.27(VCOMH)
SCL: R10D.2
SDA: R12D.2
SPI1_MOSI: R20D.2
SPI1_SCK: R19D.2
NetJP10D_20: JP10D.20(D2) R13D.1

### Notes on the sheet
- (near JP10D) OLED SSD1306: 0x3C (0x78/0x79)
- (near J10D) Note: OLED requires VBAT_SYS > 3.5V
- Ibat = 32mA max, 20mA typ
- Idd = 0.3mA
- (near R11D) BS[2:0] = 000 => 4-wire SPI
- (near R11D) BS[2:0] = 010 => I2C
- (near R14D) sets SA0 in I2C
- Licensed under CERN OHL v1.2 or later
- Copyright 2015 Andrew "bunnie" Huang
- Orchard IoT Platform (bootcamp) EVT1

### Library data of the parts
C10D C11D = Cap Semi: Capacitor (Semiconductor SIM Model); MPN: CL10A105KA8NNNC; VENDOR: Samsung; MYPN: C-105-25-X5R-0603
C12D C13D = Cap Semi: as C10B on sheet 02battery
C14D C15D = Cap Semi: Capacitor (Semiconductor SIM Model); MPN: CL21B475KAFNNNE; VENDOR: Samsung; MYPN: C-475-25-X7R-0805
J10D = CON1: Connector; MYPN: J-TP-PWRTAP-0603
JP10D = ER-OLED0.96-3W: 0.96in OLED, 128x64, white; VENDOR: EastRising; MYPN: JP-ER-OLED0.96-3W
R10D R12D R13D = Res1: Resistor; MYPN: R-000-1_4W-0402-DNP
R11D R15D R17D = Res1: as R22B on sheet 02battery
R14D R16D = Res1: Resistor; MYPN: R-103-1P-1_16W-0402-DNP
R18D = Res1: Resistor; MPN: RS02U394FT; VENDOR: Fenghua; MYPN: R-394-1P-1_16W-0402
R19D R20D = Res1: as R14M on sheet 01mcu-radio

## Sheet 05ble.SchDoc
size A4
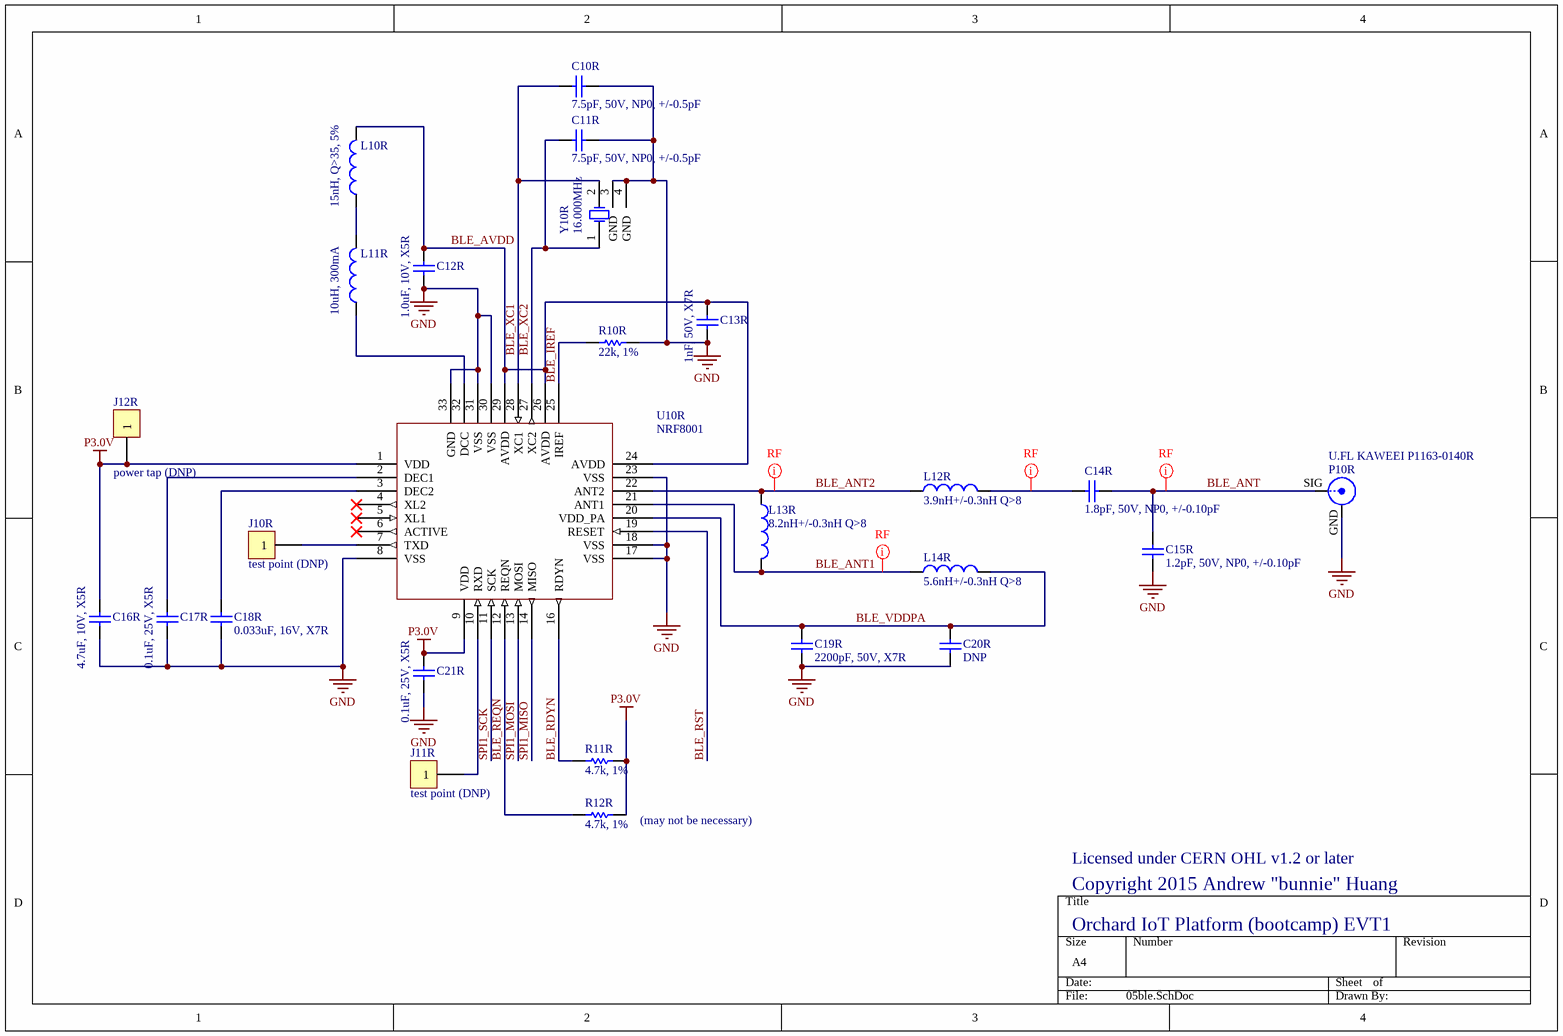
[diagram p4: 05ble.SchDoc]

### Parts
C10R  7.5pF, 50V, NP0, +/-0.5pF  [CAPC1005N]
C11R  7.5pF, 50V, NP0, +/-0.5pF  [CAPC1005N]
C12R  1.0uF, 10V, X5R  [CAPC1005N]
C13R  1nF, 50V, X7R  [CAPC1005N]
C14R  1.8pF, 50V, NP0, +/-0.10pF  [CAPC1005N]
C15R  1.2pF, 50V, NP0, +/-0.10pF  [CAPC1005N]
C16R  4.7uF, 10V, X5R  [CAPC1608N]
C17R  0.1uF, 25V, X5R  [CAPC1005N]
C18R  0.033uF, 16V, X7R  [CAPC1005N]
C19R  2200pF, 50V, X7R  [CAPC1005N]
C20R  DNP  [CAPC1005N]
C21R  0.1uF, 25V, X5R  [CAPC1005N]
J10R  test point (DNP)  [TP_SMT_38mil]
J11R  test point (DNP)  [TP_SMT_38mil]
J12R  power tap (DNP)  [RESTAP-0603]
L10R  15nH, Q>35, 5%  [INDC1608AN]
L11R  10uH, 300mA  [INDC1608AN]
L12R  3.9nH+/-0.3nH Q>8  [INDC1608AN]
L13R  8.2nH+/-0.3nH Q>8  [INDC1608AN]
L14R  5.6nH+/-0.3nH Q>8  [INDC1608AN]
P10R  U.FL KAWEEI P1163-0140R  [HRS_U.FL]
R10R  22k, 1%  [RESC1005N]
R11R  4.7k, 1%  [RESC1005N]
R12R  4.7k, 1%  [RESC1005N]
U10R  NRF8001  [QFN50P500X500-32VAN]
Y10R  16.000MHz  [NDK_NX3225SA]

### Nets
GND: C10R.2 C11R.2 C12R.2 C13R.2 C15R.1 C16R.2 C17R.2 C18R.1 C19R.1 C20R.1 C21R.2 P10R.GND(Y) R10R.1 U10R.8(VSS) U10R.17(VSS) U10R.18(VSS) U10R.23(VSS) U10R.30(VSS) U10R.31(VSS) U10R.33(GND) Y10R.3(GND) Y10R.4(GND)
P3.0V: C16R.1 C21R.1 J12R.1 R11R.2 R12R.2 U10R.1(VDD) U10R.9(VDD)
BLE_ANT: C14R.2 C15R.2 P10R.SIG(X)
BLE_ANT1: L13R.2 L14R.1 U10R.21(ANT1)
BLE_ANT2: L12R.1 L13R.1 U10R.22(ANT2)
BLE_AVDD: C12R.1 C13R.1 L10R.2 U10R.24(AVDD) U10R.26(AVDD) U10R.29(AVDD)
BLE_IREF: R10R.2 U10R.25(IREF)
BLE_RDYN: R11R.1 U10R.16(RDYN)
BLE_REQN: R12R.1 U10R.12(REQN)
BLE_RST: U10R.19(RESET)
BLE_VDDPA: C19R.2 C20R.2 L14R.2 U10R.20(VDD_PA)
BLE_XC1: C10R.1 U10R.28(XC1) Y10R.2(OSC2)
BLE_XC2: C11R.1 U10R.27(XC2) Y10R.1(OSC1)
SPI1_MISO: U10R.14(MISO)
SPI1_MOSI: U10R.13(MOSI)
SPI1_SCK: U10R.11(SCK)
NetC14R_1: C14R.1 L12R.2
NetC17R_1: C17R.1 U10R.2(DEC1)
NetC18R_2: C18R.2 U10R.3(DEC2)
NetJ10R_1: J10R.1 U10R.7(TXD)
NetJ11R_1: J11R.1 U10R.10(RXD)
NetL10R_1: L10R.1 L11R.2
NetL11R_1: L11R.1 U10R.32(DCC)

Not connected (* = marked no-connect by the designer): U10R 4(XL2)* 5(XL1)* 6(ACTIVE)*

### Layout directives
net class RF: BLE_ANT, BLE_ANT1, BLE_ANT2, NetC14R_1

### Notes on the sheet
- (near R12R) (may not be necessary)
- Licensed under CERN OHL v1.2 or later
- Copyright 2015 Andrew "bunnie" Huang
- Orchard IoT Platform (bootcamp) EVT1

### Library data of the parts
C10R C11R = Cap Semi: as C14M on sheet 01mcu-radio
C12R = Cap Semi: as C10B on sheet 02battery
C13R = Cap Semi: Capacitor (Semiconductor SIM Model); MPN: CL05B102KB5NNNC; VENDOR: Samsung; MYPN: C-102-50-X7R-0402
C14R = Cap Semi: Capacitor (Semiconductor SIM Model); MPN: 0402CG1R8B500NT; VENDOR: Fenghua; MYPN: C-1R8-50-NP0-0402
C15R = Cap Semi: Capacitor (Semiconductor SIM Model); MPN: 0402CG1R2B500NT; VENDOR: Fenghua; MYPN: C-1R2-50-NP0-0402
C16R = Cap Semi: as C33M on sheet 01mcu-radio
C17R C21R = Cap Semi: as C10M on sheet 01mcu-radio
C18R = Cap Semi: as C35M on sheet 01mcu-radio
C19R = Cap Semi: Capacitor (Semiconductor SIM Model); MPN: CL05B222KB5NNND; VENDOR: Samsung; MYPN: C-222-50-X7R-0402
C20R = Cap Semi: Capacitor (Semiconductor SIM Model)
J10R J11R = CON1: Connector; MYPN: J-TP-SMT38-TOP
J12R = CON1: Connector; MYPN: J-TP-PWRTAP-0603
L10R = Inductor: chip inductor, 0603; MPN: FHW0603UC015JGT; VENDOR: Fenghua; MYPN: L-15N-MLC-0603
L11R = Inductor: chip inductor, 0603; MPN: MLZ1608N100LT000; VENDOR: TDK Corporation; MYPN: L-10U-MLC-0603
L12R = Inductor: chip inductor, 0603; MPN: VHF160808H3N9ST; VENDOR: Fenghua; MYPN: L-3N9-MLC-0603
L13R = Inductor: chip inductor, 0603; MPN: VHF160808H8N2ST; VENDOR: Fenghua; MYPN: L-8N2-MLC-0603
L14R = Inductor: chip inductor, 0603; MPN: VHF160808H5N6ST; VENDOR: Fenghua; MYPN: L-5N6-MLC-0603
P10R = BNC: U.FL connector; MYPN: J-U.FL-A
R10R = Res1: as R11S on sheet 03sensors
R11R R12R = Res1: as R10M on sheet 01mcu-radio
U10R = NRF8001: BLE single-chip solution; MPN: NRF8001-R2Q32-T; MYPN: UNRF8001; VENDOR: Nordic Semiconductor
Y10R = XTAL: 32 MHz, 7pF CL 10ppm 3225 SMD crystal; MPN: SJSMD3216M009F10; VENDOR: Songji; MYPN: X-16.000M-SONGJI

## Sheet 06led.SchDoc
size A
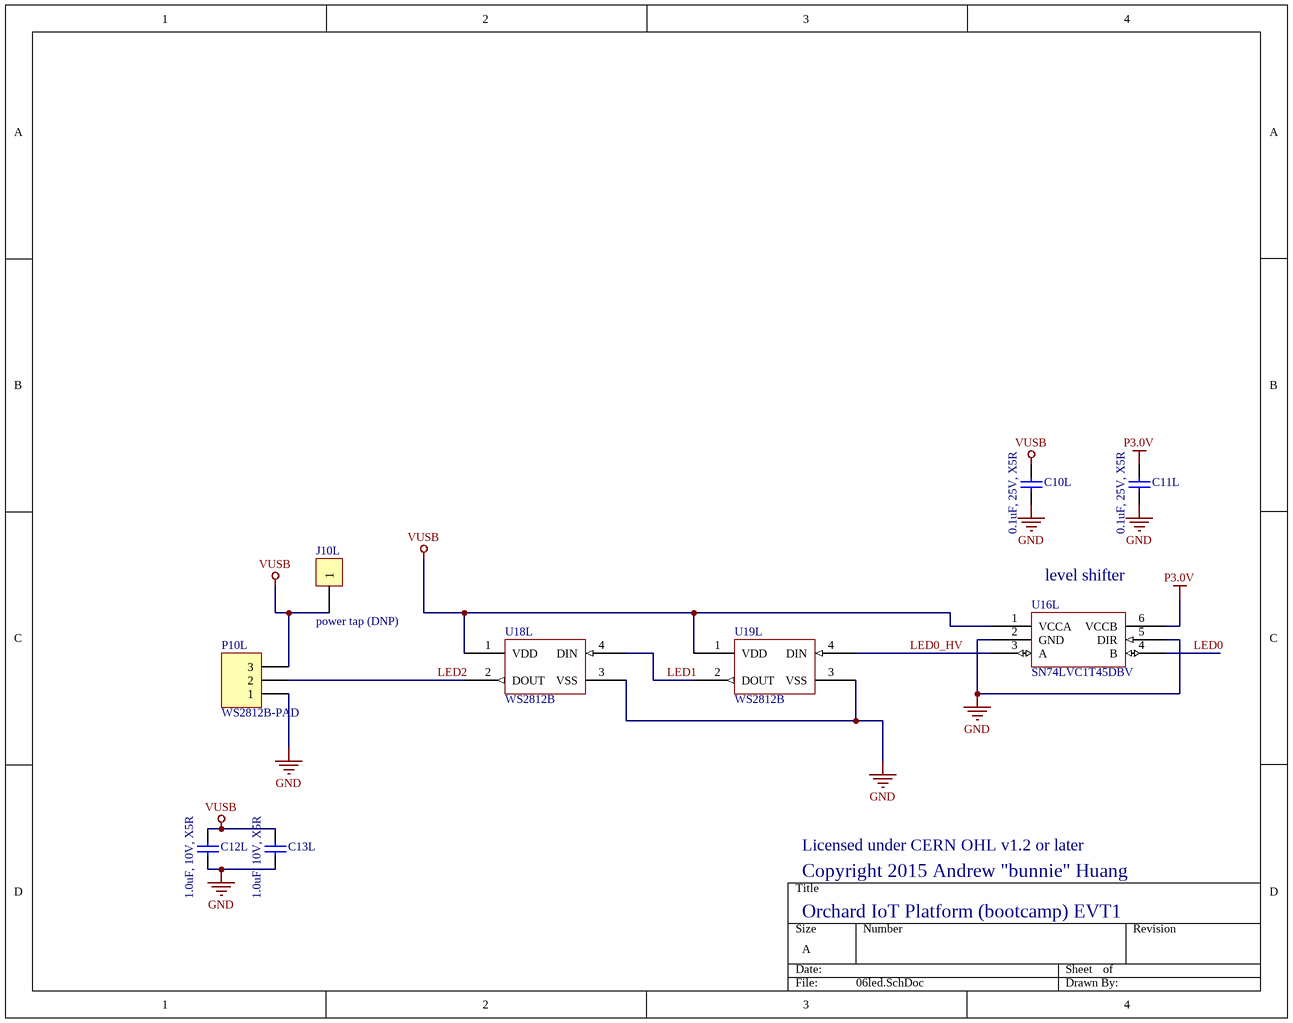
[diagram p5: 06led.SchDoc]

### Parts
C10L  0.1uF, 25V, X5R  [CAPC1005N]
C11L  0.1uF, 25V, X5R  [CAPC1005N]
C12L  1.0uF, 10V, X5R  [CAPC1005N]
C13L  1.0uF, 10V, X5R  [CAPC1005N]
J10L  power tap (DNP)  [RESTAP-0603]
P10L  WS2812B-PAD  [LED_STRIP_PADS_SHORT]
U16L  SN74LVC1T45DBV  [SOT26A-6N]
U18L  WS2812B  [WS2812B]
U19L  WS2812B  [WS2812B]

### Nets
GND: C10L.2 C11L.2 C12L.2 C13L.2 P10L.1 U16L.2(GND) U16L.5(DIR) U18L.3(VSS) U19L.3(VSS)
P3.0V: C11L.1 U16L.6(VCCB)
VUSB: C10L.1 C12L.1 C13L.1 J10L.1 P10L.3 U16L.1(VCCA) U18L.1(VDD) U19L.1(VDD)
LED0: U16L.4(B)
LED0_HV: U16L.3(A) U19L.4(DIN)
LED1: U18L.4(DIN) U19L.2(DOUT)
LED2: P10L.2 U18L.2(DOUT)

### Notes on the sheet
- (near U16L) level shifter
- Licensed under CERN OHL v1.2 or later
- Copyright 2015 Andrew "bunnie" Huang
- Orchard IoT Platform (bootcamp) EVT1

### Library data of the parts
C10L C11L = Cap Semi: as C10M on sheet 01mcu-radio
C12L C13L = Cap Semi: as C10B on sheet 02battery
J10L = CON1: Connector; MYPN: J-TP-PWRTAP-0603
P10L = Header 3: Header, 3-Pin; MPN: DNP; MYPN: PCB-WS2812B-PAD-DNP
U16L = SN74LVC1T45: Single-gate level translator; MPN: SN74LVC1T45DBVT; MYPN: USN74LVC1T45DBV; VENDOR: Texas Instruments
U18L U19L = WS2812B: RGB LED with integrated controller IC; VENDOR: Worldsemi; MYPN: UWS2812B

## Sheet 07captouch.SchDoc
size A
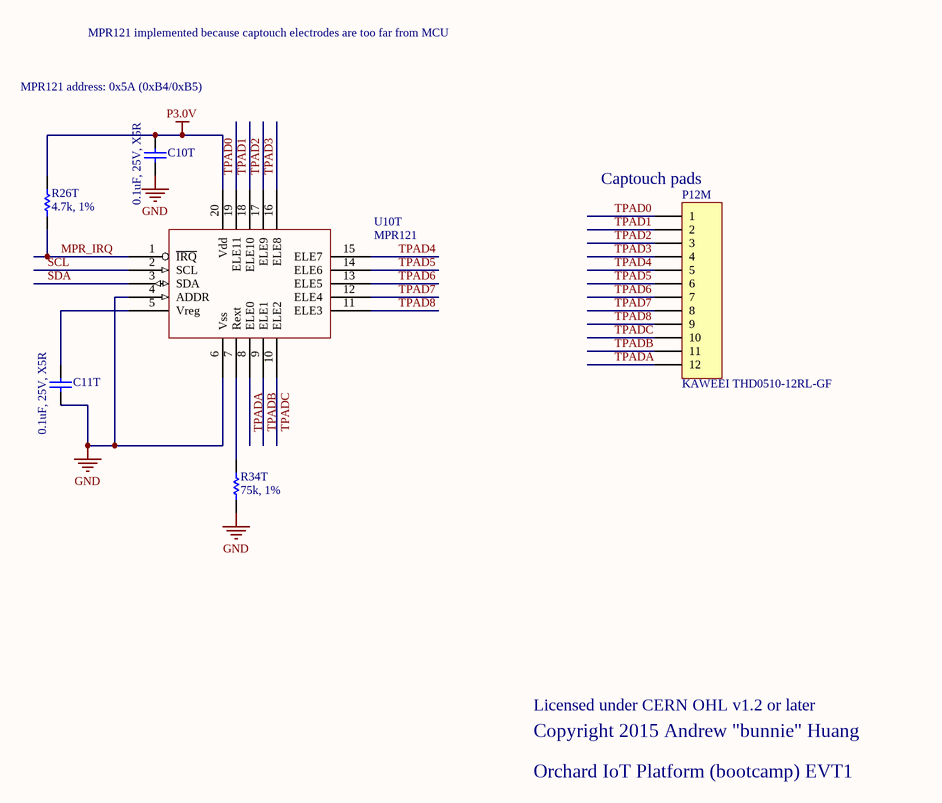
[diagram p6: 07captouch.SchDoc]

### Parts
C10T  0.1uF, 25V, X5R  [CAPC1005N]
C11T  0.1uF, 25V, X5R  [CAPC1005N]
P12M  KAWEEI THD0510-12RL-GF  [KAWEEI_THD0510_12RL_GF]
R26T  4.7k, 1%  [RESC1005N]
R34T  75k, 1%  [RESC1005N]
U10T  MPR121  [QFN40P300X300X60-20N]

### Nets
GND: C10T.2 C11T.2 R34T.1 U10T.4(ADDR) U10T.6(Vss)
P3.0V: C10T.1 R26T.2 U10T.20(Vdd)
MPR_IRQ: R26T.1 U10T.1(~{IRQ})
SCL: U10T.2(SCL)
SDA: U10T.3(SDA)
TPAD0: P12M.1 U10T.19(ELE11)
TPAD1: P12M.2 U10T.18(ELE10)
TPAD2: P12M.3 U10T.17(ELE9)
TPAD3: P12M.4 U10T.16(ELE8)
TPAD4: P12M.5 U10T.15(ELE7)
TPAD5: P12M.6 U10T.14(ELE6)
TPAD6: P12M.7 U10T.13(ELE5)
TPAD7: P12M.8 U10T.12(ELE4)
TPAD8: P12M.9 U10T.11(ELE3)
TPADA: P12M.12 U10T.8(ELE0)
TPADB: P12M.11 U10T.9(ELE1)
TPADC: P12M.10 U10T.10(ELE2)
NetC11T_1: C11T.1 U10T.5(Vreg)
NetR34T_2: R34T.2 U10T.7(Rext)

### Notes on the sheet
- MPR121 address: 0x5A (0xB4/0xB5)
- MPR121 implemented because captouch electrodes are too far from MCU
- (near P12M) Captouch pads
- Licensed under CERN OHL v1.2 or later
- Copyright 2015 Andrew "bunnie" Huang
- Orchard IoT Platform (bootcamp) EVT1

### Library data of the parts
C10T C11T = Cap Semi: as C10M on sheet 01mcu-radio
P12M = Header 12: Header, 12-Pin; MYPN: J-FPC-0.5-12-THD
R26T = Res1: as R10M on sheet 01mcu-radio
R34T = Res1: Resistor; MPN: RS02U753FT; VENDOR: Fenghua; MYPN: R-753-1P-1_16W-0402
U10T = MPR121: Freescale 12-electrode captouch switch sensor IC; MPN: MPR121QR2; VENDOR: Freescale Semiconductor; MYPN: UMPR121

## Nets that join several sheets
GND: 01mcu-radio (42 pins), 02battery (38 pins), 03sensors (17 pins), 04oled (20 pins), 05ble (22 pins), 06led (9 pins), 07captouch (5 pins)
P3.0V: 01mcu-radio (25 pins), 02battery (R19B.2 R22B.2 R29B.2 R30B.2), 03sensors (5 pins), 04oled (C13D.1 JP10D.9 R16D.1), 05ble (7 pins), 06led (C11L.1 U16L.6), 07captouch (C10T.1 R26T.2 U10T.20)
VBAT_SYS: 01mcu-radio (C33M.1 J15M.1 U12M.2 U12M.7), 02battery (10 pins), 03sensors (C10S.1 U10S.1 U10S.3), 04oled (C12D.1 J10D.1 JP10D.6)
VUSB: 01mcu-radio (D10M.2), 02battery (10 pins), 06led (8 pins)
ACCEL_INT: 01mcu-radio (U11M.7), 03sensors (U13S.11)
BAT_CD: 01mcu-radio (U11M.12), 02battery (U12B.4)
BAT_INT: 01mcu-radio (U11M.11), 02battery (R19B.1 U12B.10)
BLE_RDYN: 01mcu-radio (U10M.26), 05ble (R11R.1 U10R.16)
BLE_REQN: 01mcu-radio (U10M.7), 05ble (R12R.1 U10R.12)
BLE_RST: 01mcu-radio (U11M.5), 05ble (U10R.19)
GG_INT: 01mcu-radio (U11M.8), 02battery (Q10B.1 R22B.1 R28B.2 U13B.A1)
LED0: 01mcu-radio (U10M.6), 06led (U16L.4)
MIC_OUT: 01mcu-radio (U10M.5), 02battery (R26B.1 R27B.2), 03sensors (R10S.1)
MPR_IRQ: 01mcu-radio (U11M.3), 07captouch (R26T.1 U10T.1)
OLED_CS: 01mcu-radio (U10M.16), 04oled (JP10D.13)
OLED_DC: 01mcu-radio (U10M.17), 04oled (JP10D.15 R14D.1)
OLED_RES: 01mcu-radio (U11M.4), 04oled (JP10D.14)
SCL: 01mcu-radio (R10M.1 U10M.24 U11M.13), 02battery (U12B.16 U13B.A3), 03sensors (U13S.4), 04oled (R10D.2), 07captouch (U10T.2)
SDA: 01mcu-radio (R11M.1 U10M.25 U11M.14), 02battery (U12B.17 U13B.A2), 03sensors (U13S.6), 04oled (R12D.2), 07captouch (U10T.3)
SPI1_MISO: 01mcu-radio (U10M.32), 05ble (U10R.14)
SPI1_MOSI: 01mcu-radio (U10M.34), 04oled (R20D.2), 05ble (U10R.13)
SPI1_SCK: 01mcu-radio (U10M.28), 04oled (R19D.2), 05ble (U10R.11)
USBD_N: 01mcu-radio (R16M.1), 02battery (5 pins)
USBD_P: 01mcu-radio (R17M.1), 02battery (5 pins)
